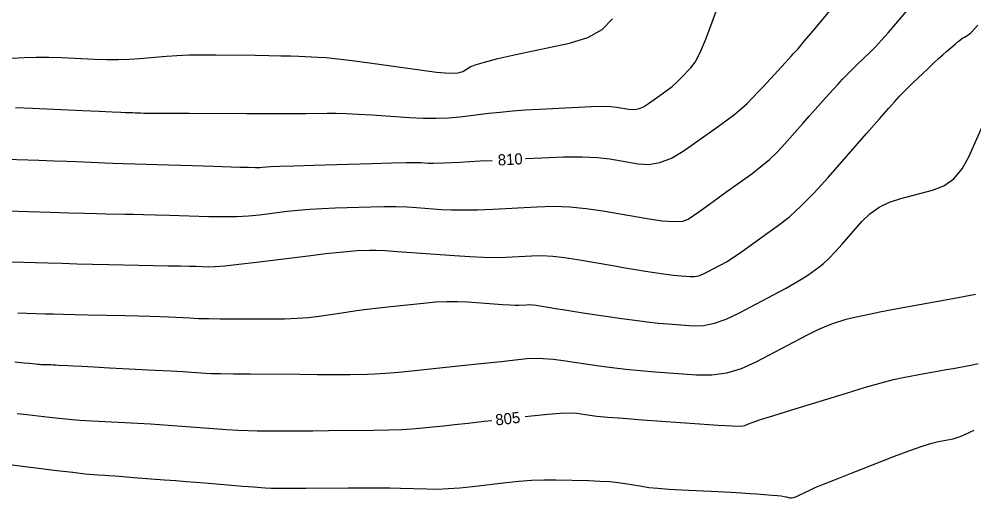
# Model space of a CAD drawing. Extents: x 2082232 to 2083549, y 592624 to 593832.
# Drawn here: x 2082395.5 to 2082455.4, y 593070.3 to 593100.4 of the extents above; entities that cross this region are included whole.
import ezdxf

# ---------------------------------------------------------------- set-up
doc = ezdxf.new("R2010")
doc.units = 0
doc.layers.add('DT_X_Contour_Major', color=7, linetype='Continuous')
doc.layers.add('DT_X_Contour_Minor', color=7, linetype='Continuous')

msp = doc.modelspace()

# ---------------------------------------------------------------- linework, layer by layer
at = {"layer": 'DT_X_Contour_Major'}
for points in [[(2082427.28, 593091.617), (2082428.318, 593091.673), (2082429.678, 593091.726), (2082430.84, 593091.73), (2082431.803, 593091.685), (2082432.569, 593091.592), (2082434.348, 593091.279), (2082435.025, 593091.241), (2082435.721, 593091.364), (2082436.437, 593091.647), (2082437.174, 593092.091), (2082439.163, 593093.489), (2082439.849, 593093.981), (2082440.414, 593094.411), (2082440.86, 593094.777), (2082441.184, 593095.081), (2082441.89, 593095.806), (2082442.153, 593096.079), (2082442.412, 593096.352), (2082442.667, 593096.626), (2082442.918, 593096.901), (2082443.583, 593097.635), (2082443.806, 593097.88), (2082443.974, 593098.064), (2082444.087, 593098.186), (2082444.146, 593098.247), (2082444.231, 593098.328), (2082444.389, 593098.511), (2082444.801, 593098.998), (2082445.465, 593099.789), (2082446.383, 593100.884)], [(2082393.947, 593091.61), (2082396.746, 593091.512), (2082397.708, 593091.478), (2082398.495, 593091.449), (2082399.107, 593091.425), (2082399.543, 593091.407), (2082400.472, 593091.366), (2082400.876, 593091.349), (2082401.392, 593091.331), (2082402.019, 593091.309), (2082402.758, 593091.286), (2082404.877, 593091.22), (2082405.649, 593091.197), (2082406.378, 593091.174), (2082407.063, 593091.154), (2082407.705, 593091.135), (2082409.357, 593091.087), (2082409.91, 593091.073), (2082410.332, 593091.066), (2082410.622, 593091.066), (2082410.78, 593091.074), (2082411.026, 593091.104), (2082411.279, 593091.119), (2082411.854, 593091.141), (2082412.751, 593091.171), (2082413.97, 593091.207), (2082417.649, 593091.314), (2082418.877, 593091.348), (2082419.801, 593091.368), (2082420.422, 593091.376), (2082420.739, 593091.37), (2082421.18, 593091.336), (2082421.507, 593091.335), (2082422.157, 593091.356), (2082423.131, 593091.4), (2082424.428, 593091.466), (2082425.183, 593091.506)], [(2082427.261, 593075.419), (2082427.667, 593075.465), (2082428.679, 593075.571), (2082429.489, 593075.633), (2082430.098, 593075.652), (2082430.504, 593075.628), (2082431.319, 593075.507), (2082431.754, 593075.455), (2082432.449, 593075.39), (2082433.403, 593075.312), (2082434.616, 593075.221), (2082438.198, 593074.96), (2082439.384, 593074.879), (2082440.254, 593074.835), (2082440.81, 593074.825), (2082441.051, 593074.852), (2082441.273, 593074.97), (2082441.506, 593075.058), (2082442.039, 593075.233), (2082442.872, 593075.497), (2082444.005, 593075.848), (2082447.425, 593076.901), (2082448.61, 593077.258), (2082449.596, 593077.538), (2082450.386, 593077.744), (2082450.979, 593077.873), (2082452.296, 593078.116), (2082452.78, 593078.205), (2082453.245, 593078.289), (2082453.69, 593078.37), (2082454.115, 593078.445), (2082455.224, 593078.641), (2082455.695, 593078.764)], [(2082395.383, 593075.621), (2082395.993, 593075.55), (2082397.421, 593075.376), (2082397.987, 593075.314), (2082398.616, 593075.257), (2082399.306, 593075.207), (2082400.059, 593075.163), (2082402.149, 593075.054), (2082402.942, 593075.01), (2082403.752, 593074.96), (2082404.58, 593074.904), (2082405.426, 593074.842), (2082407.705, 593074.668), (2082408.517, 593074.611), (2082409.243, 593074.569), (2082409.882, 593074.542), (2082410.436, 593074.531), (2082411.799, 593074.52), (2082412.378, 593074.519), (2082413.093, 593074.521), (2082413.943, 593074.528), (2082414.929, 593074.54), (2082417.739, 593074.577), (2082418.711, 593074.594), (2082419.517, 593074.618), (2082420.158, 593074.648), (2082420.634, 593074.685), (2082421.684, 593074.793), (2082422.168, 593074.844), (2082422.831, 593074.917), (2082423.675, 593075.012), (2082424.698, 593075.128), (2082425.174, 593075.182)]]:
    msp.add_lwpolyline(points, dxfattribs=at)
at = {"layer": 'DT_X_Contour_Minor'}
for points in [[(2082395.281, 593094.829), (2082396.339, 593094.784), (2082399.482, 593094.641), (2082400.534, 593094.594), (2082401.334, 593094.557), (2082401.881, 593094.533), (2082402.175, 593094.519), (2082402.621, 593094.5), (2082402.778, 593094.493), (2082402.912, 593094.487), (2082403.023, 593094.483), (2082403.113, 593094.48), (2082403.321, 593094.473), (2082403.559, 593094.471), (2082404.114, 593094.467), (2082404.988, 593094.463), (2082406.181, 593094.457), (2082409.784, 593094.443), (2082411.03, 593094.439), (2082412.064, 593094.438), (2082412.886, 593094.44), (2082413.497, 593094.445), (2082414.842, 593094.464), (2082415.395, 593094.462), (2082416.044, 593094.443), (2082416.79, 593094.408), (2082417.632, 593094.355), (2082420.005, 593094.193), (2082420.869, 593094.15), (2082421.682, 593094.143), (2082422.444, 593094.172), (2082423.154, 593094.237), (2082424.978, 593094.46), (2082425.691, 593094.539), (2082426.46, 593094.609), (2082427.285, 593094.671), (2082428.168, 593094.723), (2082430.596, 593094.852), (2082431.428, 593094.888), (2082432.106, 593094.899), (2082432.629, 593094.885), (2082432.997, 593094.846), (2082433.772, 593094.71), (2082434.066, 593094.694), (2082434.369, 593094.747), (2082434.681, 593094.871), (2082435.002, 593095.064), (2082435.868, 593095.672), (2082436.183, 593095.903), (2082436.478, 593096.141), (2082436.753, 593096.384), (2082437.008, 593096.633), (2082437.663, 593097.306), (2082437.931, 593097.675), (2082438.244, 593098.278), (2082438.603, 593099.114), (2082439.008, 593100.185), (2082440.148, 593103.351)], [(2082394.039, 593088.358), (2082397.455, 593088.254), (2082398.634, 593088.219), (2082399.607, 593088.191), (2082400.375, 593088.17), (2082400.937, 593088.157), (2082402.163, 593088.132), (2082402.682, 593088.12), (2082403.318, 593088.104), (2082404.071, 593088.083), (2082404.941, 593088.058), (2082407.418, 593087.986), (2082408.313, 593087.973), (2082409.14, 593087.986), (2082409.898, 593088.027), (2082410.587, 593088.095), (2082412.336, 593088.311), (2082413.015, 593088.386), (2082413.741, 593088.446), (2082414.515, 593088.491), (2082415.335, 593088.523), (2082417.586, 593088.589), (2082418.398, 593088.605), (2082419.145, 593088.603), (2082419.828, 593088.585), (2082420.446, 593088.549), (2082422.008, 593088.43), (2082422.649, 593088.398), (2082423.402, 593088.391), (2082424.266, 593088.408), (2082425.242, 593088.45), (2082427.992, 593088.597), (2082429.025, 593088.621), (2082430.061, 593088.587), (2082431.1, 593088.492), (2082432.141, 593088.338), (2082434.924, 593087.847), (2082435.868, 593087.708), (2082436.612, 593087.657), (2082437.156, 593087.696), (2082437.501, 593087.823), (2082438.155, 593088.283), (2082438.445, 593088.488), (2082438.826, 593088.76), (2082439.298, 593089.097), (2082439.859, 593089.501), (2082441.478, 593090.666), (2082442.062, 593091.109), (2082442.601, 593091.564), (2082443.095, 593092.032), (2082443.544, 593092.512), (2082444.681, 593093.808), (2082445.09, 593094.273), (2082445.465, 593094.697), (2082445.806, 593095.08), (2082446.113, 593095.42), (2082446.886, 593096.273), (2082447.179, 593096.591), (2082447.476, 593096.902), (2082447.778, 593097.208), (2082448.086, 593097.508), (2082448.913, 593098.301), (2082449.245, 593098.635), (2082449.623, 593099.04), (2082450.046, 593099.518), (2082450.515, 593100.068), (2082451.824, 593101.632)], [(2082394.998, 593085.137), (2082397.308, 593085.067), (2082398.196, 593085.041), (2082399.129, 593085.016), (2082400.106, 593084.993), (2082401.128, 593084.971), (2082403.914, 593084.913), (2082404.864, 593084.893), (2082405.627, 593084.877), (2082406.202, 593084.863), (2082406.589, 593084.853), (2082407.371, 593084.83), (2082407.78, 593084.842), (2082408.42, 593084.893), (2082409.292, 593084.984), (2082410.395, 593085.115), (2082413.646, 593085.519), (2082414.751, 593085.652), (2082415.629, 593085.75), (2082416.279, 593085.812), (2082416.701, 593085.839), (2082417.524, 593085.863), (2082417.919, 593085.861), (2082418.49, 593085.838), (2082419.234, 593085.794), (2082420.153, 593085.728), (2082422.836, 593085.524), (2082423.792, 593085.461), (2082424.647, 593085.425), (2082425.402, 593085.416), (2082426.056, 593085.435), (2082427.666, 593085.52), (2082428.299, 593085.53), (2082428.989, 593085.495), (2082429.737, 593085.415), (2082430.543, 593085.29), (2082432.768, 593084.898), (2082433.539, 593084.763), (2082434.182, 593084.653), (2082434.697, 593084.568), (2082435.085, 593084.507), (2082435.948, 593084.379), (2082436.259, 593084.335), (2082436.546, 593084.299), (2082436.808, 593084.271), (2082437.046, 593084.25), (2082437.647, 593084.206), (2082437.883, 593084.212), (2082438.139, 593084.264), (2082438.417, 593084.36), (2082438.715, 593084.501), (2082439.538, 593084.937), (2082439.889, 593085.139), (2082440.324, 593085.415), (2082440.842, 593085.766), (2082441.445, 593086.193), (2082443.165, 593087.43), (2082443.842, 593087.966), (2082444.586, 593088.644), (2082445.395, 593089.466), (2082446.27, 593090.43), (2082448.691, 593093.192), (2082449.492, 593094.105), (2082450.079, 593094.774), (2082450.452, 593095.197), (2082450.61, 593095.376), (2082450.747, 593095.527), (2082450.837, 593095.621), (2082451.006, 593095.787), (2082451.254, 593096.027), (2082451.579, 593096.341), (2082452.552, 593097.274), (2082452.897, 593097.603), (2082453.203, 593097.888), (2082453.468, 593098.131), (2082453.694, 593098.331), (2082454.243, 593098.805), (2082454.434, 593098.967), (2082454.594, 593099.093), (2082454.724, 593099.186), (2082454.824, 593099.245), (2082455.048, 593099.357), (2082455.246, 593099.539), (2082455.674, 593100.001)], [(2082395.04, 593097.923), (2082395.816, 593097.964), (2082396.594, 593097.983), (2082397.373, 593097.98), (2082398.154, 593097.956), (2082400.237, 593097.861), (2082401, 593097.837), (2082401.725, 593097.835), (2082402.412, 593097.856), (2082403.062, 593097.899), (2082404.744, 593098.046), (2082405.412, 593098.092), (2082406.152, 593098.122), (2082406.966, 593098.136), (2082407.853, 593098.133), (2082410.317, 593098.102), (2082411.181, 593098.09), (2082411.926, 593098.076), (2082412.551, 593098.059), (2082413.057, 593098.041), (2082414.246, 593097.99), (2082414.784, 593097.952), (2082415.506, 593097.878), (2082416.411, 593097.767), (2082417.5, 593097.62), (2082420.648, 593097.179), (2082421.702, 593097.049), (2082422.505, 593096.987), (2082423.055, 593096.996), (2082423.354, 593097.073), (2082423.815, 593097.372), (2082424.123, 593097.504), (2082424.704, 593097.676), (2082425.557, 593097.888), (2082426.682, 593098.14), (2082430.045, 593098.865), (2082431.187, 593099.215), (2082432.088, 593099.722), (2082432.749, 593100.385)], [(2082395.426, 593081.943), (2082395.958, 593081.916), (2082397.16, 593081.88), (2082397.664, 593081.865), (2082398.275, 593081.85), (2082398.993, 593081.834), (2082399.817, 593081.816), (2082402.159, 593081.768), (2082402.989, 593081.748), (2082403.723, 593081.727), (2082404.363, 593081.704), (2082404.906, 593081.679), (2082406.228, 593081.611), (2082406.772, 593081.588), (2082407.411, 593081.571), (2082408.145, 593081.56), (2082408.975, 593081.555), (2082411.316, 593081.55), (2082412.164, 593081.56), (2082412.949, 593081.593), (2082413.673, 593081.651), (2082414.336, 593081.731), (2082416.022, 593081.979), (2082416.671, 593082.07), (2082417.354, 593082.159), (2082418.072, 593082.245), (2082418.824, 593082.329), (2082420.875, 593082.548), (2082421.625, 593082.614), (2082422.337, 593082.648), (2082423.01, 593082.65), (2082423.645, 593082.619), (2082425.286, 593082.494), (2082425.847, 593082.455), (2082426.298, 593082.429), (2082426.639, 593082.417), (2082426.87, 593082.419), (2082427.34, 593082.444), (2082427.525, 593082.447), (2082427.726, 593082.437), (2082427.945, 593082.414), (2082428.18, 593082.377), (2082428.83, 593082.263), (2082429.151, 593082.209), (2082429.625, 593082.134), (2082430.253, 593082.039), (2082431.034, 593081.922), (2082433.323, 593081.582), (2082434.149, 593081.465), (2082434.91, 593081.37), (2082435.605, 593081.295), (2082436.236, 593081.24), (2082437.831, 593081.124), (2082438.456, 593081.14), (2082439.137, 593081.276), (2082439.873, 593081.531), (2082440.664, 593081.905), (2082442.847, 593083.063), (2082443.596, 593083.466), (2082444.205, 593083.807), (2082444.675, 593084.087), (2082445.004, 593084.305), (2082445.697, 593084.804), (2082445.983, 593085.034), (2082446.321, 593085.351), (2082446.711, 593085.755), (2082447.152, 593086.245), (2082448.399, 593087.667), (2082448.902, 593088.158), (2082449.476, 593088.563), (2082450.12, 593088.883), (2082450.834, 593089.117), (2082452.833, 593089.628), (2082453.538, 593089.905), (2082454.154, 593090.355), (2082454.682, 593090.978), (2082455.121, 593091.773), (2082456.172, 593094.122)], [(2082395.237, 593078.861), (2082395.827, 593078.802), (2082396.127, 593078.772), (2082396.538, 593078.73), (2082396.678, 593078.715), (2082396.788, 593078.705), (2082396.868, 593078.698), (2082396.918, 593078.695), (2082397.012, 593078.693), (2082397.052, 593078.691), (2082397.1, 593078.69), (2082397.156, 593078.689), (2082397.221, 593078.688), (2082397.404, 593078.684), (2082397.492, 593078.681), (2082397.617, 593078.676), (2082397.781, 593078.668), (2082397.982, 593078.658), (2082398.568, 593078.627), (2082398.895, 593078.61), (2082399.438, 593078.582), (2082400.195, 593078.542), (2082401.168, 593078.492), (2082404.05, 593078.341), (2082405.022, 593078.289), (2082405.779, 593078.248), (2082406.32, 593078.216), (2082406.646, 593078.195), (2082407.226, 593078.151), (2082407.562, 593078.135), (2082408.137, 593078.121), (2082408.95, 593078.11), (2082410.002, 593078.1), (2082413.124, 593078.076), (2082414.199, 593078.069), (2082415.082, 593078.065), (2082415.773, 593078.065), (2082416.272, 593078.069), (2082417.348, 593078.083), (2082417.838, 593078.101), (2082418.5, 593078.147), (2082419.336, 593078.219), (2082420.344, 593078.318), (2082423.264, 593078.618), (2082424.273, 593078.723), (2082425.112, 593078.811), (2082425.78, 593078.882), (2082426.278, 593078.937), (2082427.376, 593079.062), (2082427.836, 593079.089), (2082428.391, 593079.074), (2082429.041, 593079.018), (2082429.786, 593078.921), (2082431.9, 593078.607), (2082432.715, 593078.496), (2082433.574, 593078.396), (2082434.478, 593078.307), (2082435.426, 593078.231), (2082438.014, 593078.042), (2082438.976, 593078.039), (2082439.919, 593078.174), (2082440.844, 593078.445), (2082441.752, 593078.853), (2082444.147, 593080.123), (2082444.972, 593080.551), (2082445.651, 593080.885), (2082446.185, 593081.125), (2082446.572, 593081.269), (2082447.411, 593081.527), (2082447.855, 593081.643), (2082448.558, 593081.797), (2082449.518, 593081.989), (2082450.738, 593082.219), (2082454.334, 593082.883), (2082455.519, 593083.102)], [(2082394.892, 593072.411), (2082397.881, 593072.047), (2082398.882, 593071.926), (2082399.645, 593071.838), (2082400.168, 593071.781), (2082400.453, 593071.757), (2082400.893, 593071.734), (2082401.129, 593071.719), (2082401.506, 593071.693), (2082402.025, 593071.655), (2082402.685, 593071.605), (2082404.635, 593071.457), (2082405.341, 593071.402), (2082405.998, 593071.351), (2082406.605, 593071.301), (2082407.163, 593071.255), (2082408.583, 593071.135), (2082409.084, 593071.093), (2082409.522, 593071.057), (2082409.895, 593071.028), (2082410.205, 593071.006), (2082410.946, 593070.953), (2082411.315, 593070.937), (2082411.864, 593070.927), (2082412.595, 593070.924), (2082413.506, 593070.928), (2082416.178, 593070.946), (2082417.133, 593070.95), (2082417.994, 593070.948), (2082418.761, 593070.939), (2082419.433, 593070.925), (2082421.1, 593070.877), (2082421.747, 593070.873), (2082422.437, 593070.898), (2082423.17, 593070.951), (2082423.947, 593071.032), (2082426.075, 593071.287), (2082426.869, 593071.369), (2082427.654, 593071.422), (2082428.431, 593071.447), (2082429.199, 593071.445), (2082431.237, 593071.4), (2082431.954, 593071.376), (2082432.578, 593071.34), (2082433.108, 593071.291), (2082433.545, 593071.229), (2082434.585, 593071.046), (2082435.033, 593070.98), (2082435.598, 593070.922), (2082436.28, 593070.87), (2082437.079, 593070.824), (2082439.365, 593070.712), (2082440.16, 593070.672), (2082440.83, 593070.635), (2082441.376, 593070.601), (2082441.797, 593070.571), (2082442.754, 593070.496), (2082443.078, 593070.468), (2082443.334, 593070.441), (2082443.522, 593070.415), (2082443.64, 593070.39), (2082443.865, 593070.324), (2082443.968, 593070.317), (2082444.108, 593070.344), (2082444.286, 593070.407), (2082444.501, 593070.504), (2082445.123, 593070.809), (2082445.457, 593070.96), (2082445.993, 593071.184), (2082446.731, 593071.48), (2082447.67, 593071.85), (2082450.444, 593072.932), (2082451.397, 593073.295), (2082452.175, 593073.571), (2082452.779, 593073.761), (2082453.207, 593073.865), (2082454.118, 593074.026), (2082454.62, 593074.19), (2082455.443, 593074.563)]]:
    msp.add_lwpolyline(points, dxfattribs=at)

# ---------------------------------------------------------------- texts
at = {"layer": 'DT_X_Contour_Major'}
for s, rotation, p in [('810', 3.03991, (2082425.563, 593091.176)), ('805', 6.49381, (2082425.433, 593074.859))]:
    msp.add_text(s, height=0.7, rotation=rotation, dxfattribs=at).set_placement(p)

doc.saveas('drawing.dxf')
